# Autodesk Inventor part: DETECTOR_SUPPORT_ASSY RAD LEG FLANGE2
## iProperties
Shininess: 64.0
Length Units: 11272
Angle Units: 11279
Time Units: 11290
Mass Units: 11286
Length Display Precision: 3
Angle Display Precision: 2
Compacted: True
Part Number: DETECTOR_SUPPORT_ASSY RAD LEG FLANGE2
Document SubType Name: Modeling
Created: 2004-08
Designer: John Blackburn
Material: ALUMINUM
Manufacturer: Standard
Standards Organization: Custom
Density: 0.0
Volumn: 0.0
Area: 0.0
PropertySet Name: Model Information
Control State: 0
Master: False
Checked Out: False
Author: John Blackburn
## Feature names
1. ExtrusionBlind1
2. Hole1
3. Rectangular Pattern1
